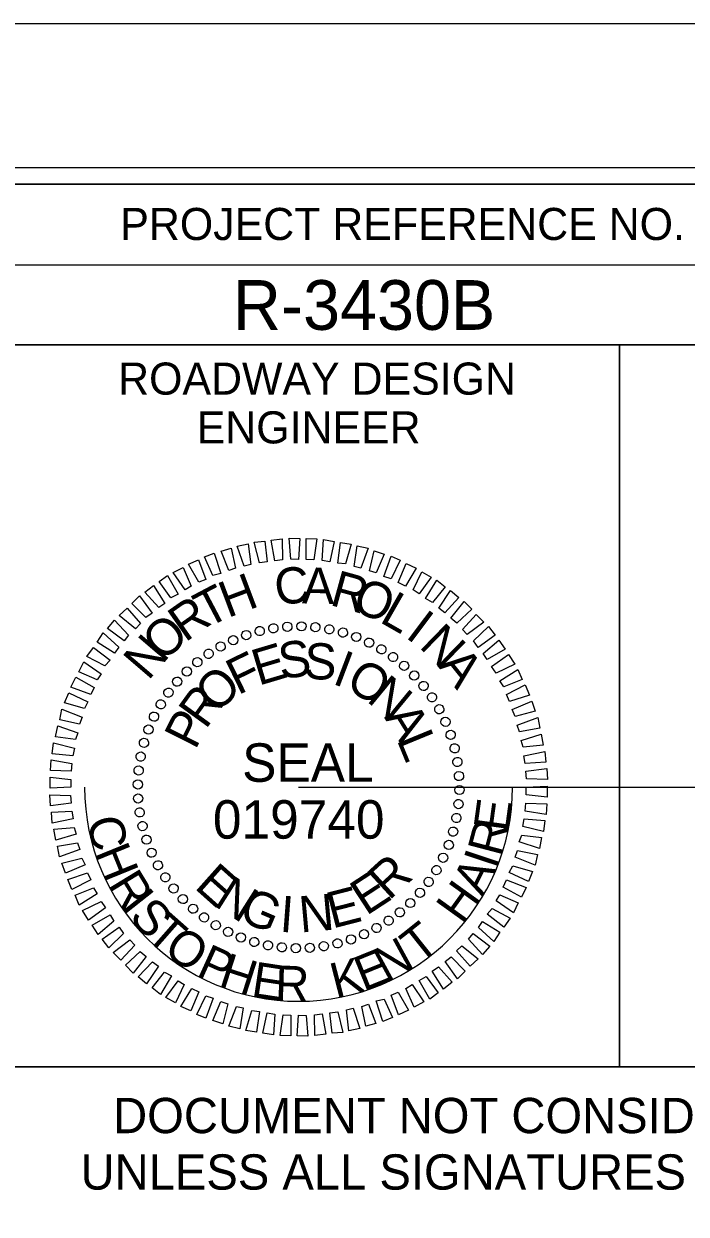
# Model space of a CAD drawing. Extents: x 1262239 to 1263984, y 747221 to 748321.
# Drawn here: x 1263712.9 to 1263816.1, y 748135.2 to 748320.7 of the extents above; entities that cross this region are included whole.
import ezdxf

# ---------------------------------------------------------------- set-up
doc = ezdxf.new("R2010")
doc.units = 0
for name, color, linetype in [('Prop Drainage Structure Bridge', 7, 'Continuous'), ('Prop Drainage Structure Bridge Opening', 7, 'Continuous'), ('Prop Grid Mask', 7, 'Continuous'), ('Prop Horizontal Alignment', 7, 'Continuous'), ('Prop Paved Shoulder', 7, 'Continuous'), ('Prop Terminator CELL', 7, 'Continuous'), ('Prop VPI Label', 7, 'Continuous'), ('Sheet Border Standard 30in CELL', 7, 'Continuous'), ('Sheet Layout Plan Border', 7, 'Continuous')]:
    doc.layers.add(name, color=color, linetype=linetype)

msp = doc.modelspace()

# ---------------------------------------------------------------- linework, layer by layer
at = {"layer": 'Prop Drainage Structure Bridge'}
for p, q in [((1263749.6, 748226.1), (1263749.6, 748226.1)), ((1263751.8, 748226.5), (1263751.8, 748226.5)), ((1263753.95, 748226.8), (1263753.95, 748226.8)), ((1263756.15, 748226.85), (1263756.15, 748226.85)), ((1263758.35, 748226.7), (1263758.35, 748226.7)), ((1263760.5, 748226.35), (1263760.5, 748226.35)), ((1263745.5, 748224.7), (1263745.5, 748224.7)), ((1263747.5, 748225.5), (1263747.5, 748225.5)), ((1263762.6, 748225.9), (1263762.6, 748225.9)), ((1263764.7, 748225.2), (1263764.7, 748225.2)), ((1263766.7, 748224.3), (1263766.7, 748224.3)), ((1263741.65, 748222.55), (1263741.65, 748222.55)), ((1263743.55, 748223.7), (1263743.55, 748223.7)), ((1263768.65, 748223.3), (1263768.65, 748223.3)), ((1263739.9, 748221.3), (1263739.9, 748221.3)), ((1263770.45, 748222.05), (1263770.45, 748222.05)), ((1263772.2, 748220.7), (1263772.2, 748220.7)), ((1263738.25, 748219.8), (1263738.25, 748219.8)), ((1263773.75, 748219.2), (1263773.75, 748219.2)), ((1263736.75, 748218.25), (1263736.75, 748218.25)), ((1263775.25, 748217.55), (1263775.25, 748217.55)), ((1263735.4, 748216.5), (1263735.4, 748216.5)), ((1263776.5, 748215.8), (1263776.5, 748215.8)), ((1263734.15, 748214.7), (1263734.15, 748214.7)), ((1263777.65, 748213.9), (1263777.65, 748213.9)), ((1263733.15, 748212.75), (1263733.15, 748212.75)), ((1263778.65, 748211.95), (1263778.65, 748211.95)), ((1263732.25, 748210.75), (1263732.25, 748210.75)), ((1263779.45, 748209.95), (1263779.45, 748209.95)), ((1263731.55, 748208.65), (1263731.55, 748208.65)), ((1263780.05, 748207.85), (1263780.05, 748207.85)), ((1263731.1, 748206.55), (1263731.1, 748206.55)), ((1263780.45, 748205.65), (1263780.45, 748205.65)), ((1263730.75, 748204.4), (1263730.75, 748204.4)), ((1263730.6, 748202.2), (1263730.6, 748202.2)), ((1263780.75, 748203.5), (1263780.75, 748203.5)), ((1263755.7, 748201.75), (1263755.7, 748201.75)), ((1263780.8, 748201.3), (1263780.8, 748201.3)), ((1263730.65, 748200), (1263730.65, 748200)), ((1263780.65, 748199.1), (1263780.65, 748199.1)), ((1263730.95, 748197.85), (1263730.95, 748197.85)), ((1263780.3, 748196.95), (1263780.3, 748196.95)), ((1263731.35, 748195.65), (1263731.35, 748195.65)), ((1263779.85, 748194.85), (1263779.85, 748194.85)), ((1263731.95, 748193.55), (1263731.95, 748193.55)), ((1263779.15, 748192.75), (1263779.15, 748192.75)), ((1263732.75, 748191.55), (1263732.75, 748191.55)), ((1263733.75, 748189.6), (1263733.75, 748189.6)), ((1263778.25, 748190.75), (1263778.25, 748190.75)), ((1263734.9, 748187.7), (1263734.9, 748187.7)), ((1263777.25, 748188.8), (1263777.25, 748188.8)), ((1263736.15, 748185.95), (1263736.15, 748185.95)), ((1263774.65, 748185.25), (1263774.65, 748185.25)), ((1263776, 748187), (1263776, 748187)), ((1263737.65, 748184.3), (1263737.65, 748184.3)), ((1263773.15, 748183.7), (1263773.15, 748183.7)), ((1263739.2, 748182.8), (1263739.2, 748182.8)), ((1263771.5, 748182.2), (1263771.5, 748182.2)), ((1263740.95, 748181.45), (1263740.95, 748181.45)), ((1263742.75, 748180.2), (1263742.75, 748180.2)), ((1263767.85, 748179.8), (1263767.85, 748179.8)), ((1263769.75, 748180.95), (1263769.75, 748180.95)), ((1263744.7, 748179.2), (1263744.7, 748179.2)), ((1263746.7, 748178.3), (1263746.7, 748178.3)), ((1263763.9, 748178), (1263763.9, 748178)), ((1263765.9, 748178.8), (1263765.9, 748178.8)), ((1263748.8, 748177.6), (1263748.8, 748177.6)), ((1263750.9, 748177.15), (1263750.9, 748177.15)), ((1263753.05, 748176.8), (1263753.05, 748176.8)), ((1263755.25, 748176.65), (1263755.25, 748176.65)), ((1263757.45, 748176.7), (1263757.45, 748176.7)), ((1263759.6, 748177), (1263759.6, 748177)), ((1263761.8, 748177.4), (1263761.8, 748177.4))]:
    msp.add_line(p, q, dxfattribs=at)
for points in [[(1263747.2, 748236.2), (1263746.15, 748239.35), (1263747.85, 748239.7), (1263748.25, 748236.45)], [(1263749.6, 748236.75), (1263748.8, 748239.95), (1263750.45, 748240.1), (1263750.8, 748236.9)], [(1263752, 748237.05), (1263751.45, 748240.25), (1263753.15, 748240.45), (1263753.2, 748237.2)], [(1263754.5, 748237.3), (1263754.25, 748240.55), (1263755.9, 748240.5), (1263755.7, 748237.25)], [(1263756.9, 748237.25), (1263756.9, 748240.5), (1263758.55, 748240.45), (1263758.1, 748237.2)], [(1263759.4, 748237.1), (1263759.6, 748240.35), (1263761.25, 748240.05), (1263760.6, 748236.9)], [(1263761.8, 748236.7), (1263762.25, 748239.9), (1263763.9, 748239.65), (1263763, 748236.55)], [(1263764.35, 748236.15), (1263764.85, 748239.4), (1263766.55, 748239), (1263765.4, 748235.9)], [(1263740.15, 748233.7), (1263738.55, 748236.5), (1263740.1, 748237.2), (1263741.25, 748234.15)], [(1263742.35, 748234.75), (1263741.05, 748237.65), (1263742.55, 748238.25), (1263743.6, 748235.05)], [(1263744.8, 748235.55), (1263743.65, 748238.55), (1263745.2, 748239), (1263745.85, 748235.9)], [(1263766.75, 748235.5), (1263767.5, 748238.6), (1263769.05, 748238.1), (1263767.8, 748235.15)], [(1263769, 748234.6), (1263770.15, 748237.75), (1263771.55, 748237.15), (1263770.15, 748234.25)], [(1263738, 748232.5), (1263736.15, 748235.2), (1263737.7, 748236), (1263738.95, 748233.1)], [(1263771.25, 748233.65), (1263772.5, 748236.6), (1263774.05, 748235.9), (1263772.35, 748233.1)], [(1263773.55, 748232.5), (1263774.9, 748235.35), (1263776.4, 748234.5), (1263774.5, 748231.9)], [(1263735.8, 748231.25), (1263733.95, 748233.8), (1263735.25, 748234.75), (1263736.9, 748231.85)], [(1263775.5, 748231.15), (1263777.25, 748234.05), (1263778.55, 748233), (1263776.6, 748230.55)], [(1263731.9, 748228.2), (1263729.7, 748230.4), (1263730.9, 748231.6), (1263732.85, 748228.9)], [(1263733.9, 748229.75), (1263731.75, 748232.15), (1263733.1, 748233.2), (1263734.85, 748230.4)], [(1263777.55, 748229.65), (1263779.4, 748232.4), (1263780.7, 748231.3), (1263778.5, 748228.95)], [(1263779.45, 748228.1), (1263781.5, 748230.7), (1263782.7, 748229.5), (1263780.4, 748227.35)], [(1263730.25, 748226.45), (1263727.7, 748228.5), (1263728.95, 748229.65), (1263731.05, 748227.25)], [(1263781.25, 748226.35), (1263783.4, 748228.7), (1263784.6, 748227.5), (1263782, 748225.55)], [(1263728.5, 748224.55), (1263725.9, 748226.5), (1263727, 748227.8), (1263729.2, 748225.45)], [(1263783, 748224.55), (1263785.3, 748226.8), (1263786.35, 748225.45), (1263783.7, 748223.55)], [(1263727, 748222.65), (1263724.3, 748224.35), (1263725.25, 748225.8), (1263727.65, 748223.6)], [(1263784.5, 748222.6), (1263786.95, 748224.7), (1263787.9, 748223.25), (1263785.1, 748221.65)], [(1263725.5, 748220.65), (1263722.7, 748222.15), (1263723.7, 748223.55), (1263726.3, 748221.55)], [(1263785.8, 748220.55), (1263788.45, 748222.45), (1263789.4, 748220.95), (1263786.5, 748219.55)], [(1263724.3, 748218.5), (1263721.45, 748219.75), (1263722.2, 748221.3), (1263724.9, 748219.45)], [(1263723.3, 748216.2), (1263720.2, 748217.35), (1263720.95, 748218.9), (1263723.8, 748217.3)], [(1263787.1, 748218.35), (1263789.9, 748220.1), (1263790.55, 748218.55), (1263787.7, 748217.4)], [(1263788.1, 748216.2), (1263791.05, 748217.7), (1263791.7, 748216.1), (1263788.6, 748215.1)], [(1263722.3, 748214), (1263719.2, 748214.9), (1263719.85, 748216.45), (1263722.85, 748215.05)], [(1263789, 748213.85), (1263792.05, 748215.15), (1263792.6, 748213.6), (1263789.5, 748212.8)], [(1263721.55, 748211.6), (1263718.45, 748212.25), (1263718.8, 748213.9), (1263721.95, 748212.65)], [(1263720.9, 748209.2), (1263717.8, 748209.6), (1263718.15, 748211.3), (1263721.3, 748210.25)], [(1263789.8, 748211.45), (1263793, 748212.6), (1263793.3, 748210.95), (1263790.15, 748210.4)], [(1263790.4, 748209.05), (1263793.55, 748210), (1263793.85, 748208.3), (1263790.7, 748208)], [(1263720.5, 748206.65), (1263717.3, 748206.95), (1263717.5, 748208.65), (1263720.75, 748207.85)], [(1263720.25, 748204.25), (1263717, 748204.35), (1263717.1, 748206), (1263720.35, 748205.45)], [(1263790.85, 748206.65), (1263794.1, 748207.35), (1263794.25, 748205.65), (1263791.05, 748205.45)], [(1263791.15, 748204.25), (1263794.4, 748204.65), (1263794.5, 748202.95), (1263791.25, 748203.05)], [(1263720.2, 748201.75), (1263716.95, 748201.6), (1263716.95, 748203.3), (1263720.2, 748202.95)], [(1263720.25, 748199.25), (1263717, 748198.85), (1263716.9, 748200.55), (1263720.15, 748200.45)], [(1263791.2, 748201.75), (1263794.45, 748201.9), (1263794.45, 748200.2), (1263791.2, 748200.55)], [(1263791.15, 748199.25), (1263794.4, 748199.15), (1263794.3, 748197.5), (1263791.05, 748198.05)], [(1263720.55, 748196.85), (1263717.3, 748196.15), (1263717.15, 748197.85), (1263720.35, 748198.05)], [(1263790.9, 748196.85), (1263794.1, 748196.55), (1263793.9, 748194.85), (1263790.65, 748195.65)], [(1263721, 748194.45), (1263717.85, 748193.5), (1263717.55, 748195.2), (1263720.7, 748195.5)], [(1263721.6, 748192.05), (1263718.4, 748190.9), (1263718.1, 748192.55), (1263721.25, 748193.1)], [(1263790.5, 748194.3), (1263793.6, 748193.9), (1263793.25, 748192.2), (1263790.1, 748193.25)], [(1263789.85, 748191.9), (1263792.95, 748191.25), (1263792.6, 748189.6), (1263789.45, 748190.85)], [(1263722.4, 748189.65), (1263719.35, 748188.35), (1263718.8, 748189.9), (1263721.9, 748190.7)], [(1263789.1, 748189.5), (1263792.2, 748188.6), (1263791.55, 748187.05), (1263788.55, 748188.45)], [(1263723.3, 748187.3), (1263720.35, 748185.8), (1263719.7, 748187.4), (1263722.8, 748188.4)], [(1263788.1, 748187.3), (1263791.2, 748186.15), (1263790.45, 748184.6), (1263787.6, 748186.2)], [(1263724.3, 748185.15), (1263721.5, 748183.4), (1263720.85, 748184.95), (1263723.7, 748186.1)], [(1263725.6, 748182.95), (1263722.95, 748181.05), (1263722, 748182.55), (1263724.9, 748183.95)], [(1263787.1, 748185), (1263789.95, 748183.75), (1263789.2, 748182.2), (1263786.5, 748184.05)], [(1263726.9, 748180.9), (1263724.45, 748178.8), (1263723.5, 748180.25), (1263726.3, 748181.85)], [(1263785.9, 748182.85), (1263788.7, 748181.35), (1263787.7, 748179.95), (1263785.1, 748181.95)], [(1263728.4, 748178.95), (1263726.1, 748176.7), (1263725.05, 748178.05), (1263727.7, 748179.95)], [(1263784.4, 748180.85), (1263787.1, 748179.15), (1263786.15, 748177.7), (1263783.75, 748179.9)], [(1263730.15, 748177.15), (1263728, 748174.8), (1263726.8, 748176), (1263729.4, 748177.95)], [(1263782.9, 748178.95), (1263785.5, 748177), (1263784.4, 748175.7), (1263782.2, 748178.05)], [(1263731.95, 748175.4), (1263729.9, 748172.8), (1263728.7, 748174), (1263731, 748176.15)], [(1263781.15, 748177.05), (1263783.7, 748175), (1263782.45, 748173.85), (1263780.35, 748176.25)], [(1263733.85, 748173.85), (1263732, 748171.1), (1263730.7, 748172.2), (1263732.9, 748174.55)], [(1263779.5, 748175.3), (1263781.7, 748173.1), (1263780.5, 748171.9), (1263778.55, 748174.6)], [(1263735.9, 748172.35), (1263734.15, 748169.45), (1263732.85, 748170.5), (1263734.8, 748172.95)], [(1263775.6, 748172.25), (1263777.45, 748169.7), (1263776.15, 748168.75), (1263774.5, 748171.65)], [(1263777.5, 748173.75), (1263779.65, 748171.35), (1263778.3, 748170.3), (1263776.55, 748173.1)], [(1263737.85, 748171), (1263736.5, 748168.15), (1263735, 748169), (1263736.9, 748171.6)], [(1263740.15, 748169.85), (1263738.9, 748166.9), (1263737.35, 748167.6), (1263739.05, 748170.4)], [(1263773.4, 748171), (1263775.25, 748168.3), (1263773.7, 748167.5), (1263772.45, 748170.4)], [(1263742.4, 748168.9), (1263741.25, 748165.75), (1263739.85, 748166.35), (1263741.25, 748169.25)], [(1263769.05, 748168.75), (1263770.35, 748165.85), (1263768.85, 748165.25), (1263767.8, 748168.45)], [(1263771.25, 748169.8), (1263772.85, 748167), (1263771.3, 748166.3), (1263770.15, 748169.35)], [(1263744.65, 748168), (1263743.9, 748164.9), (1263742.35, 748165.4), (1263743.6, 748168.35)], [(1263747.05, 748167.35), (1263746.55, 748164.1), (1263744.85, 748164.5), (1263746, 748167.6)], [(1263749.6, 748166.8), (1263749.15, 748163.6), (1263747.5, 748163.85), (1263748.4, 748166.95)], [(1263761.8, 748166.75), (1263762.6, 748163.55), (1263760.95, 748163.4), (1263760.6, 748166.6)], [(1263764.2, 748167.3), (1263765.25, 748164.15), (1263763.55, 748163.8), (1263763.15, 748167.05)], [(1263766.6, 748167.95), (1263767.75, 748164.95), (1263766.2, 748164.5), (1263765.55, 748167.6)], [(1263752, 748166.4), (1263751.8, 748163.15), (1263750.15, 748163.45), (1263750.8, 748166.6)], [(1263754.5, 748166.25), (1263754.5, 748163), (1263752.85, 748163.05), (1263753.3, 748166.3)], [(1263756.9, 748166.2), (1263757.15, 748162.95), (1263755.5, 748163), (1263755.7, 748166.25)], [(1263759.4, 748166.45), (1263759.95, 748163.25), (1263758.25, 748163.05), (1263758.2, 748166.3)]]:
    msp.add_lwpolyline(points, close=True, dxfattribs=at)
for centre, major_axis in [((1263747.54, 748225.47), (-0.234, 0.681)), ((1263749.64, 748226.09), (-0.174, 0.699)), ((1263751.78, 748226.52), (-0.113, 0.711)), ((1263753.95, 748226.77), (-0.05, 0.718)), ((1263756.14, 748226.83), (0.013, 0.72)), ((1263758.32, 748226.7), (0.075, 0.716)), ((1263760.49, 748226.37), (0.137, 0.707)), ((1263762.62, 748225.86), (0.198, 0.692)), ((1263743.54, 748223.69), (-0.349, 0.63)), ((1263745.5, 748224.66), (-0.293, 0.658)), ((1263764.69, 748225.17), (0.258, 0.672)), ((1263766.7, 748224.29), (0.316, 0.647)), ((1263741.68, 748222.55), (-0.403, 0.597)), ((1263768.62, 748223.25), (0.371, 0.617)), ((1263770.44, 748222.04), (0.423, 0.582)), ((1263738.28, 748219.79), (-0.5, 0.518)), ((1263739.92, 748221.24), (-0.453, 0.56)), ((1263772.16, 748220.68), (0.472, 0.543)), ((1263736.77, 748218.21), (-0.543, 0.472)), ((1263773.74, 748219.17), (0.518, 0.5)), ((1263735.41, 748216.49), (-0.582, 0.423)), ((1263775.19, 748217.54), (0.56, 0.453)), ((1263734.21, 748214.67), (-0.617, 0.371)), ((1263776.5, 748215.78), (0.597, 0.403)), ((1263733.16, 748212.75), (-0.647, 0.316)), ((1263777.64, 748213.91), (0.63, 0.349)), ((1263732.29, 748210.74), (-0.672, 0.258)), ((1263778.61, 748211.95), (0.658, 0.293)), ((1263731.59, 748208.67), (-0.692, 0.198)), ((1263779.42, 748209.92), (0.681, 0.234)), ((1263780.04, 748207.82), (0.699, 0.174)), ((1263731.08, 748206.54), (-0.707, 0.137)), ((1263780.47, 748205.68), (0.711, 0.113)), ((1263730.76, 748204.37), (-0.716, 0.075)), ((1263780.72, 748203.5), (0.718, 0.05)), ((1263730.63, 748202.19), (-0.72, 0.013)), ((1263780.78, 748201.32), (0.72, -0.013)), ((1263730.68, 748200), (-0.718, -0.05)), ((1263730.93, 748197.83), (-0.711, -0.113)), ((1263780.65, 748199.13), (0.716, -0.075)), ((1263731.37, 748195.69), (-0.699, -0.174)), ((1263780.32, 748196.97), (0.707, -0.137)), ((1263779.81, 748194.84), (0.692, -0.198)), ((1263731.99, 748193.59), (-0.681, -0.234)), ((1263779.12, 748192.76), (0.672, -0.258)), ((1263732.79, 748191.55), (-0.658, -0.293)), ((1263778.24, 748190.76), (0.647, -0.316)), ((1263733.77, 748189.59), (-0.63, -0.349)), ((1263777.2, 748188.84), (0.617, -0.371)), ((1263734.91, 748187.73), (-0.597, -0.403)), ((1263775.99, 748187.01), (0.582, -0.423)), ((1263736.21, 748185.97), (-0.56, -0.453)), ((1263774.63, 748185.3), (0.543, -0.472)), ((1263737.66, 748184.33), (-0.518, -0.5)), ((1263739.25, 748182.82), (-0.472, -0.543)), ((1263773.12, 748183.71), (0.5, -0.518)), ((1263740.96, 748181.46), (-0.423, -0.582)), ((1263769.73, 748180.96), (0.403, -0.597)), ((1263771.49, 748182.26), (0.453, -0.56)), ((1263742.79, 748180.26), (-0.371, -0.617)), ((1263744.71, 748179.21), (-0.316, -0.647)), ((1263765.9, 748178.84), (0.293, -0.658)), ((1263767.86, 748179.82), (0.349, -0.63)), ((1263746.71, 748178.34), (-0.258, -0.672)), ((1263748.79, 748177.64), (-0.198, -0.692)), ((1263750.92, 748177.13), (-0.137, -0.707)), ((1263761.77, 748177.42), (0.174, -0.699)), ((1263763.87, 748178.04), (0.234, -0.681)), ((1263753.08, 748176.81), (-0.075, -0.716)), ((1263755.27, 748176.68), (-0.013, -0.72)), ((1263757.45, 748176.73), (0.05, -0.718)), ((1263759.63, 748176.98), (0.113, -0.711))]:
    msp.add_ellipse(centre, major_axis=major_axis, ratio=0.999708, dxfattribs=at)
at = {"layer": 'Prop Drainage Structure Bridge Opening'}
msp.add_line((1263922.75, 748320.74), (1262238.75, 748320.74), dxfattribs=at)
at = {"layer": 'Prop Grid Mask'}
for q in [(1263984.4, 748201.75), (1263755.7, 748201.75)]:
    msp.add_line((1263755.7, 748201.75), q, dxfattribs=at)
at = {"layer": 'Prop Horizontal Alignment'}
msp.add_arc((1263755.7, 748201.75), 33.36, 180, 360, dxfattribs=at)
at = {"layer": 'Prop Paved Shoulder'}
for p, q in [((1263705.7, 748283.19), (1263905.75, 748283.19)), ((1263805.75, 748270.69), (1263805.75, 748158.24))]:
    msp.add_line(p, q, dxfattribs=at)
for points in [[(1263905.75, 748295.74), (1262405.75, 748295.74), (1262405.75, 747245.74), (1263905.75, 747245.74)], [(1263705.7, 748295.74), (1263905.75, 748295.74), (1263905.75, 748270.69), (1263705.7, 748270.69)], [(1263705.7, 748270.69), (1263805.75, 748270.69), (1263805.75, 748158.19), (1263705.7, 748158.19)], [(1263805.75, 748270.69), (1263905.75, 748270.69), (1263905.75, 748158.19), (1263805.75, 748158.19)]]:
    msp.add_lwpolyline(points, close=True, dxfattribs=at)
at = {"layer": 'Prop Terminator CELL'}
msp.add_lwpolyline([(1263918.25, 748298.29), (1262251.75, 748298.29), (1262251.75, 747243.19), (1263918.25, 747243.19)], close=True, dxfattribs=at)
at = {"layer": 'Prop VPI Label'}
msp.add_lwpolyline([(1263922.75, 748320.74), (1262238.75, 748320.74), (1262238.75, 747220.74), (1263922.75, 747220.74)], close=True, dxfattribs=at)
at = {"layer": 'Sheet Layout Plan Border'}
msp.add_line((1263705.7, 748158.19), (1263905.74, 748158.19), dxfattribs=at)

# ---------------------------------------------------------------- texts
at = {"layer": 'Prop Drainage Structure Bridge'}
for s, height, rotation, p in [('C', 5.64, 6.2199, (1263752.25, 748230.1)), ('A', 5.64, 359.0203, (1263756.2, 748230.4)), ('R', 5.64, 344.6211, (1263760.4, 748230.2)), ('T', 5.64, 27.8198, (1263741.4, 748226.45)), ('H', 5.64, 20.6195, (1263744.65, 748228.1)), ('O', 5.64, 337.4212, (1263763.75, 748229.45)), ('L', 5.64, 330.2209, (1263768.15, 748227.6)), ('R', 5.64, 35.0205, (1263738, 748224.25)), ('O', 5.64, 42.2217, (1263734.55, 748221.15)), ('I', 5.64, 323.0201, (1263772.2, 748225.2)), ('N', 5.64, 315.8189, (1263774.35, 748223.65)), ('N', 5.64, 49.4235, (1263732.25, 748218.25)), ('E', 5.64, 16.6111, (1263749.45, 748217.55)), ('S', 5.64, 7.2556, (1263752.9, 748218.6)), ('S', 5.64, 357.9004, (1263756.5, 748218.65)), ('F', 5.64, 25.967, (1263746.25, 748216.05)), ('I', 5.64, 339.1896, (1263760.8, 748217.95)), ('A', 5.64, 308.6172, (1263777.3, 748220.7)), ('O', 5.64, 329.8335, (1263762.8, 748217.25)), ('O', 5.64, 44.6812, (1263742.95, 748213.1)), ('N', 5.64, 320.4766, (1263766.15, 748215.25)), ('R', 5.64, 54.0397, (1263741.2, 748210.65)), ('P', 5.64, 63.3989, (1263739.6, 748207.45)), ('A', 5.64, 301.7603, (1263769, 748212.65)), ('L', 5.64, 292.4008, (1263770.95, 748209.2)), ('SEAL', 5.998, 360, (1263746.9, 748202.6)), ('019740', 5.998, 360, (1263742.34, 748193.74)), ('E', 5.5, 82.1825, (1263788.41, 748194.66)), ('C', 5.5, 283.2464, (1263722.63, 748196.62)), ('R', 5.5, 75.2561, (1263787.31, 748190.76)), ('H', 5.5, 292.1191, (1263723.82, 748191.58)), ('R', 5.64, 42.4814, (1263769.8, 748184)), ('I', 5.5, 71.7356, (1263786.58, 748188.84)), ('R', 5.5, 301.3639, (1263725.87, 748186.59)), ('E', 5.64, 318.2769, (1263739.3, 748186.1)), ('A', 5.5, 63.5498, (1263784.42, 748184.58)), ('N', 5.64, 327.634, (1263742.3, 748183.4)), ('E', 5.64, 33.1241, (1263766.25, 748181.65)), ('H', 5.5, 54.305, (1263781.29, 748180.19)), ('I', 5.5, 308.2904, (1263727.92, 748183.11)), ('G', 5.64, 336.9902, (1263746.1, 748181.15)), ('E', 5.64, 14.4118, (1263760.95, 748179.7)), ('S', 5.5, 311.8108, (1263729.11, 748181.44)), ('I', 5.64, 355.7012, (1263752.65, 748179.25)), ('N', 5.64, 5.0564, (1263756, 748179.1)), ('T', 5.5, 318.5942, (1263731.7, 748178.44)), ('T', 5.5, 38.5631, (1263774.48, 748174.05)), ('O', 5.5, 324.8909, (1263734.4, 748175.94)), ('N', 5.5, 28.6314, (1263769.42, 748171.23)), ('P', 5.5, 335.5954, (1263739.57, 748172.44)), ('E', 5.5, 22.0484, (1263765.83, 748169.86)), ('H', 5.5, 342.1784, (1263743.03, 748170.78)), ('E', 5.5, 351.4232, (1263748.17, 748169.15)), ('K', 5.5, 14.3778, (1263761.49, 748168.79)), ('R', 5.5, 358.0062, (1263751.96, 748168.5))]:
    msp.add_text(s, height=height, rotation=rotation, dxfattribs=at).set_placement(p)
at = {"layer": 'Prop Paved Shoulder'}
for s, height, p in [('PROJECT REFERENCE NO.', 5.0001, (1263727.9, 748287.04)), ('ROADWAY DESIGN', 5.0001, (1263727.56, 748262.94)), ('ENGINEER', 5, (1263739.81, 748255.34))]:
    msp.add_text(s, height=height, dxfattribs=at).set_placement(p)
at = {"layer": 'Sheet Border Standard 30in CELL'}
msp.add_text('R-3430B', height=7.75, dxfattribs=at).set_placement((1263745.47, 748273.04))
at = {"layer": 'Sheet Layout Plan Border'}
for s, p in [('DOCUMENT NOT CONSIDERED FINAL', (1263726.78, 748147.84)), ('UNLESS ALL SIGNATURES COMPLETED', (1263721.7, 748139.04))]:
    msp.add_text(s, height=5.5, dxfattribs=at).set_placement(p)

doc.saveas('drawing.dxf')
